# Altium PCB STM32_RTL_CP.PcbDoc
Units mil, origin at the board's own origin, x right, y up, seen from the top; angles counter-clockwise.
Board outline 3149.08 x 3872.9 mil, 2 copper layers (Top Layer, Bottom Layer); 75 components, 87 nets, 399 pads, 171 vias.
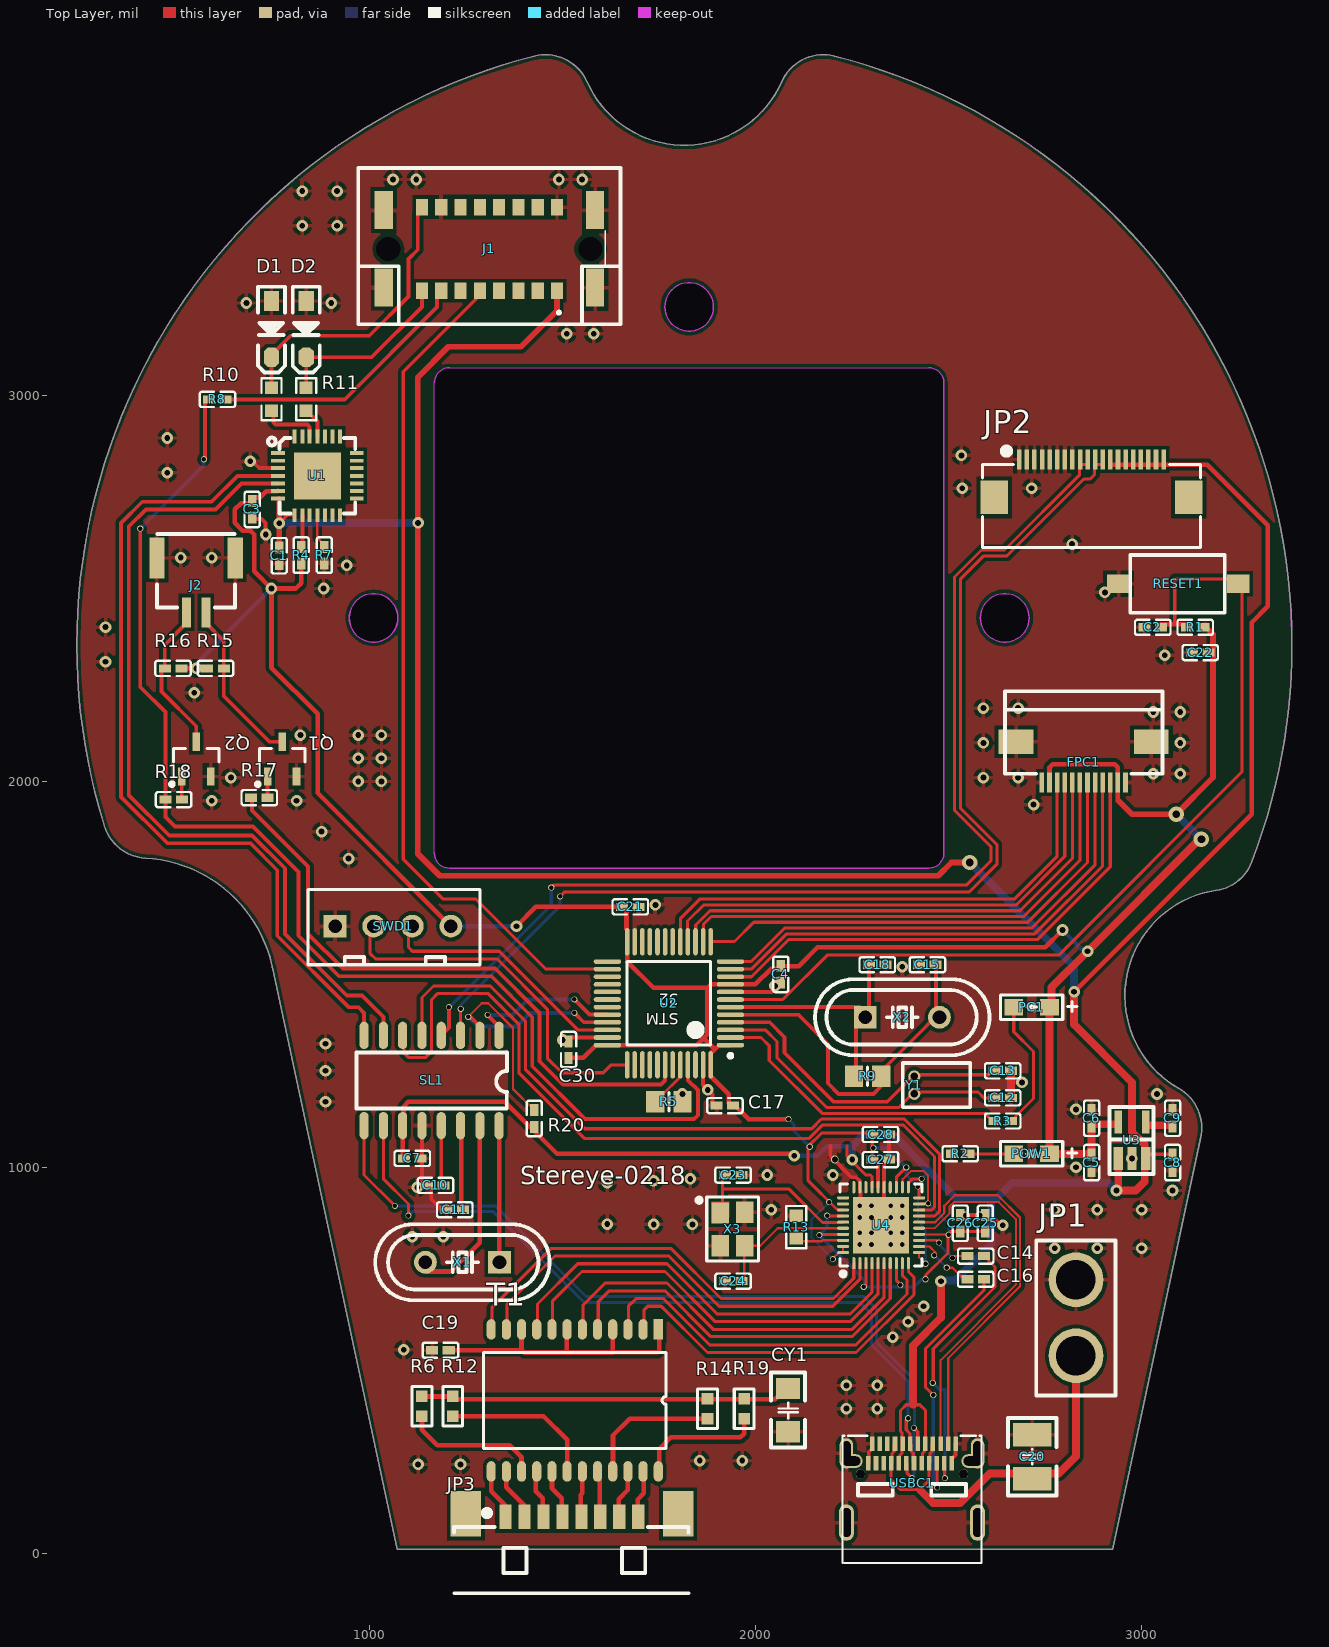
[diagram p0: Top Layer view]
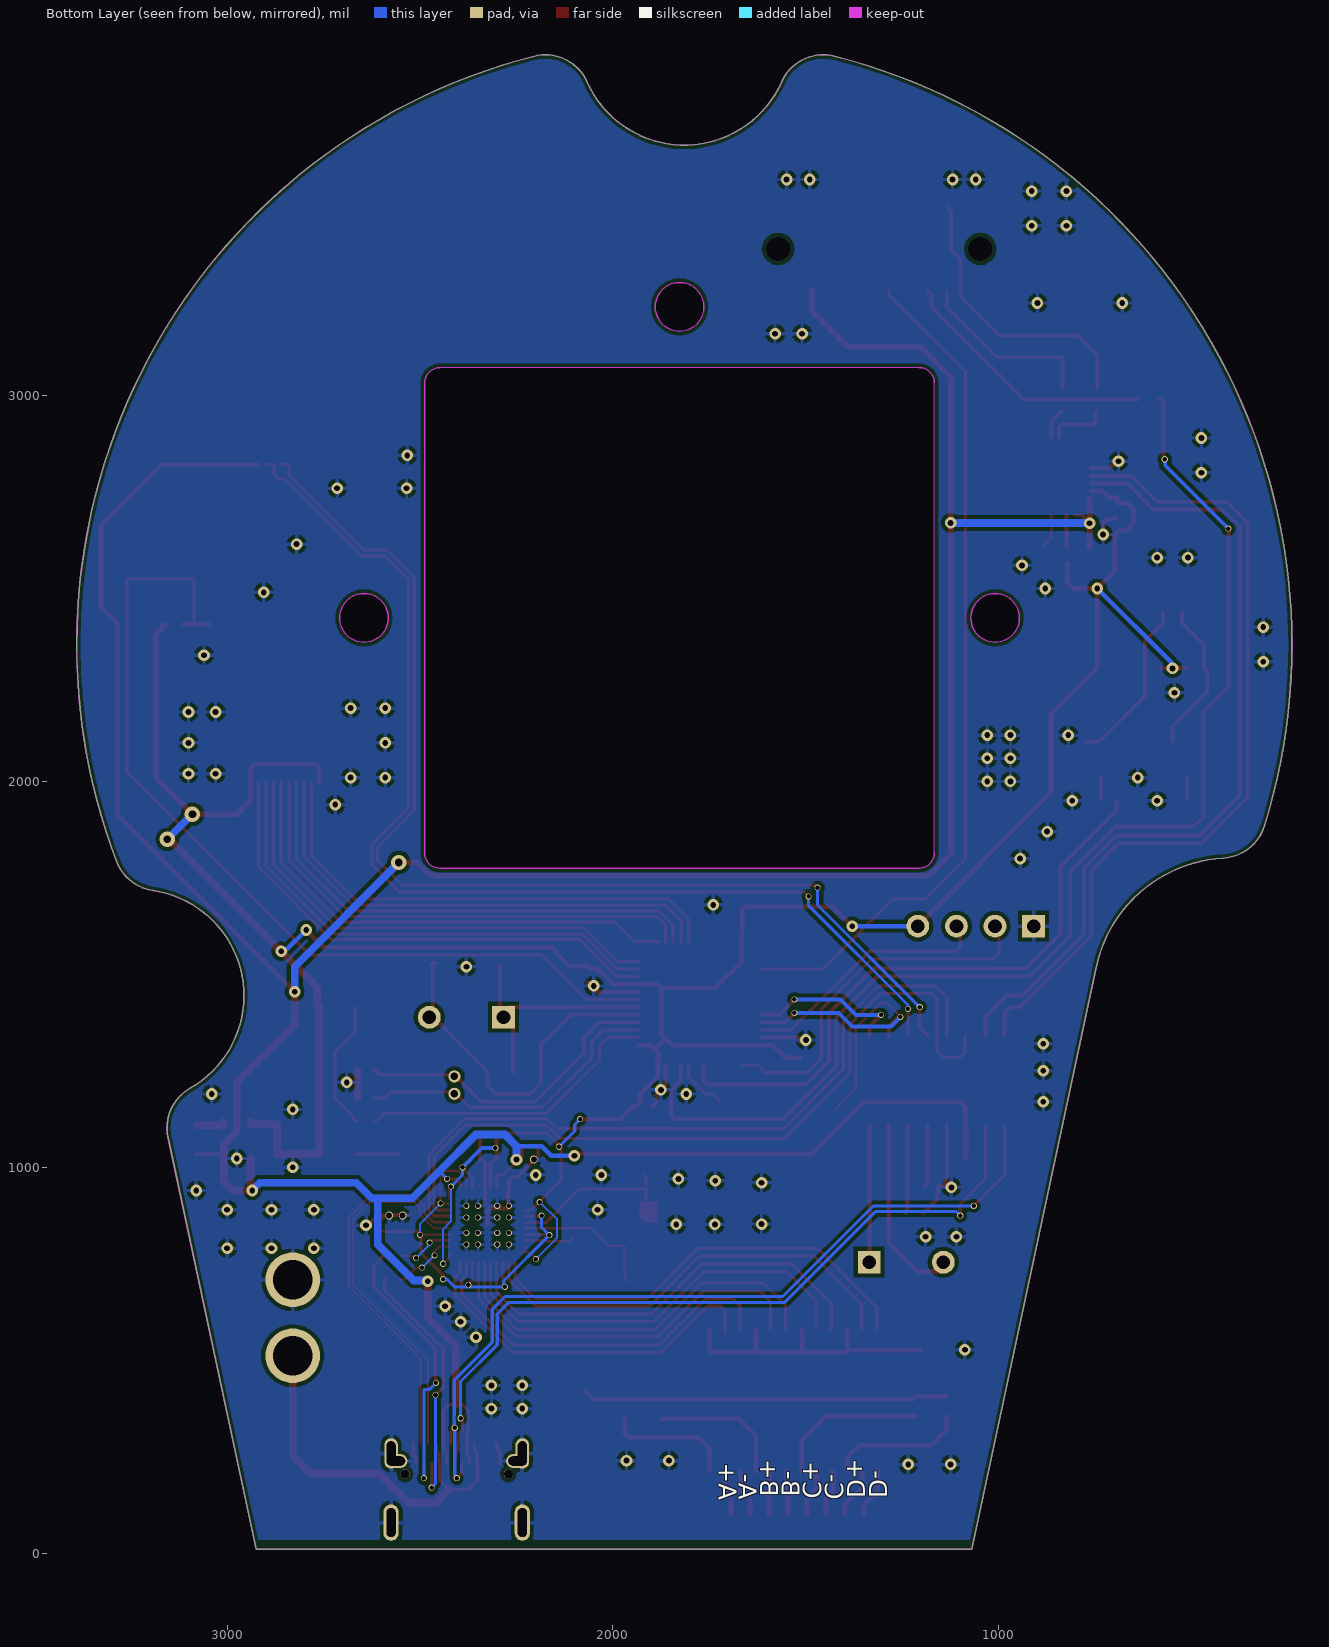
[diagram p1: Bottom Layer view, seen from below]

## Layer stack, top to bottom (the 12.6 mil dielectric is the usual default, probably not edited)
Top Solder: solder mask 0.4, Solder Resist, Dk 3.5
Top Layer: signal copper 1.4
Dielectric 1: dielectric 12.6, FR-4, Dk 4.8
Bottom Layer: signal copper 1.4
Bottom Solder: solder mask 0.4, Solder Resist, Dk 3.5

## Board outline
748.37,1514.68 ccw(c397.73,1444.47) 746.38,1523.97 ccw(c746.12,1523.91) 746.38,1523.97 ccw(c397.73,1444.47) 418.07,1801.49 cw(c424.77,1919.15) 312.29,1883.97 ccw(c312.04,1883.89) 312.29,1883.98 cw(c1815.05,2353.96) 1425.91,3879.65 cw(c1455.03,3765.46) 1425.92,3879.65 cw(c1455.03,3765.46) 1562.8,3813.15 ccw(c1815.05,3924.79) 2067.31,3813.15 cw(c2175.07,3765.46) 2204.19,3879.65 cw(c2175.07,3765.46) 2204.2,3879.65 cw(c1815.05,2353.96) 3389.59,2353.96 cw(c1815.05,2353.96) 3285.91,1792.04 ccw(c3286.15,1791.94) 3285.91,1792.03 ccw(c3286.15,1791.94) 3285.9,1792.03 ccw(c3175.82,1834.09) 3285.91,1792.03 3285.9,1792.03 cw(c3175.82,1834.09) 3192.76,1717.47 cw(c3175.82,1834.09) 3192.75,1717.47 ccw(c3232.38,1444.47) 3096.13,1204.61 cw(c3037.93,1102.14) 3155.77,1102.14 cw(c3037.93,1102.14) 3153.16,1077.48 cw(c3037.93,1102.14) 3153.16,1077.47 cw(c3153.42,1077.42) 3153.16,1077.48 3153.16,1077.47 2924.69,10.27 1070.44,10.27
cut-out: 2645.34,2360.98 cw(c2645.34,2423.98) 2582.34,2423.98 cw(c2645.34,2423.98) 2645.34,2486.97 cw(c2645.34,2423.98) 2708.33,2423.98 cw(c2645.34,2423.98)
cut-out: 1009.66,2360.98 cw(c1009.66,2423.98) 946.67,2423.98 cw(c1009.66,2423.98) 1009.66,2486.97 cw(c1009.66,2423.98) 1072.65,2423.98 cw(c1009.66,2423.98)
cut-out: 1827.5,3166.98 cw(c1827.5,3229.97) 1764.51,3229.97 cw(c1827.5,3229.97) 1827.5,3292.96 cw(c1827.5,3229.97) 1890.49,3229.97 cw(c1827.5,3229.97)
cut-out: 1206.51,1775.46 cw(c1206.51,1814.83) 1167.14,1814.83 1167.14,3033.12 cw(c1206.51,3033.12) 1206.51,3072.49 2448.49,3072.49 cw(c2448.49,3033.12) 2487.86,3033.12 2487.86,1814.83 cw(c2448.49,1814.83) 2448.49,1775.46

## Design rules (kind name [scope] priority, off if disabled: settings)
Clearance [All] p1: gap=5 ignorepadtopadclearanceinfootprint=FALSE except(10: Arc-Fill Arc-Poly Arc-Region Track-Fill Track-Poly Track-Region SMDPad-Fill SMDPad-Poly SMDPad-Region THPad-Fill THPad-Poly THPad-Region Via-Fill Via-Poly Via-Region Fill-Fill Fill-Poly Fill-Region Poly-Poly Poly-Region Region-Region)
DiffPairsRouting [All] p1: maxlimit=50 minlimit=5 mostfreqgap=5 toplayer_minwidth=5 toplayer_maxwidth=20 toplayer_prefwidth=8 bottomlayer_minwidth=5 bottomlayer_maxwidth=20 bottomlayer_prefwidth=8 maxuncoupledlength=500
PolygonConnect [All] p1: connectstyle=Relief reliefconductorwidth=10 reliefentries=4 polygonreliefangle="90 Angle" airgapwidth=10
RoutingVias [All] p1: holewidth=11.81 width=15.75 viastyle="Through Hole" minholewidth=11.81 minwidth=15.75 maxholewidth=28 maxwidth=50
SolderMaskExpansion [All] p1: expansion=4
Width All [All] p1: maxlimit=100 minlimit=5 preferedwidth=10 minimp=50.000000 maximp=50.000000 favimp=50.000000
Width VCC [InNet('5V')] p2: maxlimit=100 minlimit=5 preferedwidth=10
29 further rules are at their usual default settings.

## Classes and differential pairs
differential pair SSTX: +SSTX_P -SSTX_N
differential pair MDI3: +MDI3_P -MDI3_N
differential pair MDI2: +MDI2_P -MDI2_N
differential pair MDI1: +MDI1_P -MDI1_N
differential pair MDI0: +MDI0_P -MDI0_N
differential pair SSRX: +SSRX_P -SSRX_N
differential pair USB3-D: +USB3-D_P -USB3-D_N
differential pair D3: +D3_P -D3_N
differential pair D2: +D2_P -D2_N
differential pair D1: +D1_P -D1_N

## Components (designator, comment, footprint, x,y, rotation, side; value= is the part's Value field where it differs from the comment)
C1 "10UF" C0402_NEW 765,2585 r270 top
C2 "105" C0402_NEW 3029,2399.41 r0 top
C3 "10UF" C0402_NEW 695,2705 r90 top
C4 "104" C0402_NEW 2065,1500 r90 top
C5 "106" C0402_NEW 2870.43,1012.24 r270 top
C6 "104" C0402_NEW 2870.43,1127.24 r270 top
C7 "104" C0402_NEW 1110,1023 r180 top
C8 "105" C0402_NEW 3080.43,1012.24 r90 top
C9 "223" C0402_NEW 3080.43,1127.24 r270 top
C10 "10uF" C0402_NEW 1170,953 r0 top
C11 "10uF" C0402_NEW 1220,890.08 r0 top
C12 "22P" C0402_NEW 2640,1180 r0 top
C13 "22P" C0402_NEW 2640,1250 r0 top
C14 "0.1uF" C0402_NEW 2570,770 r0 top
C15 "22P" C0402_NEW 2445,1525 r180 top
C16 "0.1uF" C0402_NEW 2570,710 r0 top
C17 "10nf" C0402_NEW 1920,1160 r0 top
C18 "22P" C0402_NEW 2315,1525 r0 top
C19 "0.1UF" C0402_NEW 1183,526 r180 top
C20 "104" "C 1210_L" 2716.77,250 r270 top
C21 "105" C0402_NEW 1675,1675 r180 top
C22 "105" C0402_NEW 3152,2334 r0 top
C23 "30PF" C0402_NEW 1941.26,980 r0 top
C24 "30PF" C0402_NEW 1941.26,705 r0 top
C25 "10nf" C0402_NEW 2595,855 r270 top
C26 "0.1uf" C0402_NEW 2530,855 r270 top
C27 "10nf" C0402_NEW 2323.54,1020 r180 top
C28 "0.1uf" C0402_NEW 2323.54,1085 r180 top
C30 "10nf" C0402_NEW 1515,1305 r270 top
CY1 "10nF/1KV" "C 1206_L" 2084,370 r90 top
D1 "FFM107" SOD-123F 745,3172.17 r270 top
D2 "FFM107" SOD-123F 835,3172.17 r270 top
FPC1 "FPC-12P" FPC-0.5MM-12P 2850,2050 r0 top
J1 "254587" MH-16 1310,3380 r180 top
J2 "GH1.25_2P" GH1.25_2P 550,2537.99 r180 top
JP1 "HDR-1X2" XT30 2830,610 r90 top
JP2 "HDR-1X20" "FPC0.5 2H-WS-20P" 2870,2736 r0 top
JP3 "HDR-1X8" "MX 1.25-WS-8P" 1524,-16 r0 top
PC1 "LEDgreen" LED 2715,1415 r0 top
POW1 "LEDred" LED 2715,1035 r0 top
Q1 "SI2302" SOT23-3N 772.6,2057.99 r0 top
Q2 "SI2302" SOT23-3N 550,2057.99 r0 top
R1 "10K,0603" C0402_NEW 3139,2399.41 r0 top
R2 "510R,0603" C0402_NEW 2530,1035 r180 top
R3 "510R,0603" C0402_NEW 2640,1120 r180 top
R4 "5k" C0402_NEW 822,2586.54 r270 top
R5 "10K,0603" 6-0805_N 1775,1170 r0 top
R6 "1K" "R 0603_L" 1135,380.59 r270 top
R7 "5k" C0402_NEW 882,2586.54 r270 top
R8 "5k" C0402_NEW 605,2990 r180 top
R9 "1M" 6-0805_N 2290,1236.13 r0 top
R10 "68R,0603" R0603_NEW 745,2990.35 r270 top
R11 "68R,0603" R0603_NEW 835,2990.35 r270 top
R12 "1K" "R 0603_L" 1215,380.59 r270 top
R13 "2.49k" R0603_NEW 2105,845 r90 top
R14 "1K" "R 0603_L" 1875,374.41 r270 top
R15 "510R,0603" C0402_NEW 600,2292.99 r180 top
R16 "510R,0603" C0402_NEW 490,2292.99 r0 top
R17 "68R,0603" C0402_NEW 713.54,1957.99 r180 top
R18 "68R,0603" C0402_NEW 491.46,1952.99 r180 top
R19 "1K" "R 0603_L" 1970,374.41 r270 top
R20 "5k" C0402_NEW 1426,1126.54 r90 top
RESET1 "SW-PB" Key 2940.46,2512.05 r180 top
SL1 "SL2.1A" SOP-16_L10.0-W3.9-P1.27-LS6.0-BL 1160,1225 r180 top
SWD1 "SWD" HDR1X4H 910,1625 r0 top
T1 "SG24002g" SG24002 1747.48,580 r270 top
U1 "CP2102" CP2102-28G 864,2792 r0 top
U2 "STM32F103C8T6" STM32-48P 1775,1425 r180 top
U3 "RT9193-33GB" SOT-23-5 2975,1070 r0 top
U4 "RTL8153B-VB-CG" QFN-40_L5.0-W5.0-P0.40-BL-EP3.7 2325,850 r0 top
USBC1 "TypeC SMD" USB-C-SMD_MC-312D-C 2405,139.69 r0 top
X1 "12MHz" XTAL 1240,754.01 r180 top
X2 "8MHz" XTAL 2380,1388.94 r0 top
X3 "25MHz" OSC-SMD_4P-L3.2-W2.5-BL 1940,840 r90 top
Y1 "32.768K" XLAT-32 2410.98,1235.5 r270 top

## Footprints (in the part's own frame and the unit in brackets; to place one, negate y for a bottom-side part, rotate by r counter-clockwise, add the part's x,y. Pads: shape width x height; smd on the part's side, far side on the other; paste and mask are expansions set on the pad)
6-0805_N [mm] "Chip Resistor, Body 2.0x1.2mm, IPC Medium Density"
  rect 1.2x1.4 smd: 1(-0.9,0) 2(0.9,0)
  silkscreen extent 0,-0.6 0,0.6, body extent -1.07,-0.7 1.07,0.7, height 0.7
C0402_NEW [mm]
  rect 0.79x0.54 smd: 1(-0.545,0) 2(0.545,0)
  silkscreen extent -1.17,-0.5 1.17,0.5
"C 1206_L" [mil] "无极性贴片电容"
  rect 55x62 smd: 1(-55.12,0) 2(57.09,0)
  silkscreen extent -96,-44 98,44, body extent -63,-32 63,32, height 48
"C 1210_L" [mil] "无极性贴片电容                                淘宝ID:黄晶宝石"
  rect 60x100 smd: 1(-57.09,0) 2(57.09,0)
  silkscreen extent -100,-63 100,63, body extent -63,-51 63,51, height 60
CP2102-28G [mil]
  rect 35.4x10 smd: 1(-102,59) 2(-102,39) 3(-102,20) 4(-102,0) 5(-102,-20) 6(-102,-39) 7(-102,-59) 15(102,-59) 16(102,-39) 17(102,-20) 18(102,0) 19(102,20) 20(102,39) 21(102,59)
  rect 10x35.4 smd: 8(-59,-102) 9(-39,-102) 10(-20,-102) 11(0,-102) 12(20,-102) 13(39,-102) 14(59,-102) 22(59,102) 23(39,102) 24(20,102) 25(0,102) 26(-20,102) 27(-39,102) 28(-59,102)
  rect 122x122 smd: 29(0,0)
  silkscreen extent -128,-98 98,99
"FPC0.5 2H-WS-20P" [mm] "长：14.2mm，宽：5.2mm，高：2mm  淘宝ID:黄晶宝石   店铺网址:https://shop463601444.taobao.com"
  rect 1.8x2.2 smd: 0(-6.4,0) 0(6.4,0)
  rect 0.3x1.3 smd: 1(-4.75,2.497) 2(-4.25,2.497) 3(-3.75,2.497) 4(-3.25,2.497) 5(-2.75,2.497) 6(-2.25,2.497) 7(-1.75,2.497) 8(-1.25,2.497) 9(-0.75,2.497) 10(-0.25,2.497) 11(0.25,2.497) 12(0.75,2.497) 13(1.25,2.497) 14(1.75,2.497) 15(2.25,2.497) 16(2.75,2.497) 17(3.25,2.497) 18(3.75,2.497) 19(4.25,2.497) 20(4.75,2.497)
  silkscreen extent -7.18,-3.3 7.18,3.23, body extent -7.1,-3.15 7.1,2.85, height 2
FPC-0.5MM-12P [mm]
  rect 0.3x1.3 smd: 1(-2.751,-1.341) 2(-2.252,-1.341) 3(-1.751,-1.341) 4(-1.251,-1.341) 5(-0.751,-1.341) 6(-0.25,-1.341) 7(0.25,-1.341) 8(0.749,-1.341) 9(1.248,-1.341) 10(1.749,-1.341) 11(2.249,-1.341) 12(2.75,-1.341)
  rect 2.286x1.6 smd: 13(4.45,1.34) 14(-4.45,1.34)
  silkscreen extent -5.18,-0.76 5.18,4.67
GH1.25_2P [mm]
  rect 0.6x2 smd: 1(-0.635,2.54) 2(0.635,2.54)
  rect 1x2.7 smd: 3(2.585,-1.041) 4(-2.565,-1.041)
  silkscreen extent -2.55,-2.62 2.57,2.21
HDR1X4H [mm] "Connector; Header; 4 Position; Right Angle"
  rect 1.5x1.5 hole 0.9: 1(0,0)
  round 1.5 hole 0.9: 2(2.54,0) 3(5.08,0) 4(7.62,0)
  silkscreen extent -1.78,-2.54 9.52,2.41
Key [mil]
  rect 59.06x47.24 smd: 1(0,0) 2(-310,0)
  silkscreen extent -275,-75 -30,75
LED [mil]
  rect 49x43 smd: 1(46.26,0) 2(-46.26,0)
  silkscreen extent -81,-31 118,31
MH-16 [mm]
  rect 0.8x1.1 smd: A1(4.445,-2.75) A2(3.175,-2.75) A3(1.905,-2.75) A4(0.635,-2.75) A5(-0.635,-2.75) A6(-1.905,-2.75) A7(-3.175,-2.75) A8(-4.445,-2.75) B1(4.445,2.75) B2(3.175,2.75) B3(1.905,2.75) B4(0.635,2.75) B5(-0.635,2.75) B6(-1.905,2.75) B7(-3.175,2.75) B8(-4.445,2.75)
  round 0.8 hole 1.6 unplated: MH1(-6.655,0) MH2(6.655,0)
  rect 1.2x2.5 smd: MP1(-6.955,2.55) MP2(-6.955,-2.55) MP3(6.955,2.55) MP4(6.955,-2.55)
  silkscreen extent -8.64,-5.33 8.64,4.95, body extent -7.62,-3.5 7.62,3.5, height 6.7
"MX 1.25-WS-8P" [mm] "长：15.15mm，宽：4.2mm，高：3.4mm"
  rect 2x3 smd: 0(-7,3) 0(7,3)
  rect 0.8x1.6 smd: 1(-4.389,2.811) 2(-3.139,2.811) 3(-1.889,2.811) 4(-0.639,2.811) 5(0.611,2.811) 6(1.861,2.811) 7(3.111,2.811) 8(4.361,2.811)
  silkscreen extent -7.77,-2.23 7.67,3.25, body extent -7.57,-2.1 7.57,3.09, height 3.4
OSC-SMD_4P-L3.2-W2.5-BL [mm]
  rect 1.4x1.15 smd: 1(1.059,0.8) 2(-1.1,0.8) 3(-1.1,-0.8) 4(1.1,-0.8)
  Top Layer region: 1.8,0.225 0.762,0.225 0.4,0.604 0.4,1.375 1.8,1.375
  silkscreen extent -2.1,-1.7 2.1,2.35
QFN-40_L5.0-W5.0-P0.40-BL-EP3.7 [mm]
  oval 0.2x0.8 smd: 1(-1.8,-2.499) 2(-1.4,-2.499) 3(-1,-2.499) 4(-0.6,-2.499) 5(-0.2,-2.499) 6(0.2,-2.499) 7(0.6,-2.499) 8(1,-2.499) 9(1.4,-2.499) 10(1.8,-2.499) 21(1.8,2.499) 22(1.4,2.499) 23(1,2.499) 24(0.6,2.499) 25(0.2,2.499) 26(-0.2,2.499) 27(-0.6,2.499) 28(-1,2.499) 29(-1.4,2.499) 30(-1.8,2.499)
  oval 0.8x0.2 smd: 11(2.499,-1.8) 12(2.499,-1.4) 13(2.499,-1) 14(2.499,-0.6) 15(2.499,-0.2) 16(2.499,0.2) 17(2.499,0.6) 18(2.499,1) 19(2.499,1.4) 20(2.499,1.8) 31(-2.499,1.8) 32(-2.499,1.4) 33(-2.499,1) 34(-2.499,0.6) 35(-2.499,0.2) 36(-2.499,-0.2) 37(-2.499,-0.6) 38(-2.499,-1) 39(-2.499,-1.4) 40(-2.499,-1.8)
  rect 3.7x3.7 smd: 41(0,0)
  silkscreen extent -2.7,-3.35 2.7,2.7
R0603_NEW [mil]
  rect 31.75x34.02 smd: 1(-29.65,0) 2(29.66,0)
  silkscreen extent -55,-26 55,26
"R 0603_L" [mil] "1/10W贴片电阻                 淘宝ID:黄晶宝石"
  rect 30x30 smd: 1(-25.59,0) 2(25.59,0)
  silkscreen extent -51,-26 51,26, body extent -31,-16 32,16, height 16
SG24002 [mm]
  rect 1.35x0.6 smd: 1(0,0)
  oval 1.35x0.6 smd: 2(0,-1) 3(0,-2) 4(0,-3) 5(0,-4) 6(0,-5) 7(0,-6) 8(0,-7) 9(0,-8) 10(0,-9) 11(0,-10) 12(0,-11) 13(9.35,-11) 14(9.35,-10) 15(9.35,-9) 16(9.35,-8) 17(9.35,-7) 18(9.35,-6) 19(9.35,-5) 20(9.35,-4) 21(9.35,-3) 22(9.35,-2) 23(9.35,-1) 24(9.35,0)
  silkscreen extent 1.51,-11.5 7.84,0.5
SOD-123F [mm] "2.7x1.6X1.1mm（长宽高，不包括引脚）"
  rect 1.3x1 smd: 1(-1.85,0)
  oct 1.3x1 smd: 2(1.85,0)
  silkscreen extent -2.79,-0.89 2.84,0.89, body extent -1.9,-0.8 1.9,0.8, height 1.15
SOP-16_L10.0-W3.9-P1.27-LS6.0-BL [mm]
  oval 0.6x1.8 smd: 1(-4.445,-2.972) 2(-3.175,-2.972) 3(-1.905,-2.972) 4(-0.635,-2.972) 5(0.635,-2.972) 6(1.905,-2.972) 7(3.175,-2.972) 8(4.445,-2.972) 9(4.445,2.972) 10(3.175,2.972) 11(1.905,2.972) 12(0.635,2.972) 13(-0.635,2.972) 14(-1.905,2.972) 15(-3.175,2.972) 16(-4.445,2.972)
  silkscreen extent -4.95,-1.85 4.95,1.85
SOT23-3N [mm] "3x1.3x1mm(长宽高)    封装库来自淘宝卖家 ID：黄晶宝石"
  rect 0.5x1.2 smd: 1(-0.95,-1.143) 2(0.95,-1.143) 3(0,1.143)
  silkscreen extent -1.72,-1.78 1.5,0.7, body extent -1.5,-1.2 1.5,1.2, height 1.05
SOT-23-5 [mm]
  rect 0.6x1.5 smd: 1(-0.9,-1.2) 2(0,-1.2)
  rect 0.63x1.5 smd: 3(0.9,-1.2)
  rect 0.5x1.5 smd: 4(0.9,1.2) 5(-0.9,1.2)
  silkscreen extent -1.47,-2.21 1.43,2.18
STM32-48P [mm]
  oval 1.8x0.3 smd: 1(-4.05,2.75) 2(-4.05,2.25) 3(-4.05,1.75) 4(-4.05,1.25) 5(-4.05,0.75) 6(-4.05,0.25) 7(-4.05,-0.25) 8(-4.05,-0.75) 9(-4.05,-1.25) 10(-4.05,-1.75) 11(-4.05,-2.25) 12(-4.05,-2.75) 25(4.05,-2.75) 26(4.05,-2.25) 27(4.05,-1.75) 28(4.05,-1.25) 29(4.05,-0.75) 30(4.05,-0.25) 31(4.05,0.25) 32(4.05,0.75) 33(4.05,1.25) 34(4.05,1.75) 35(4.05,2.25) 36(4.05,2.75)
  oval 0.3x1.8 smd: 13(-2.75,-4.05) 14(-2.25,-4.05) 15(-1.75,-4.05) 16(-1.25,-4.05) 17(-0.75,-4.05) 18(-0.25,-4.05) 19(0.25,-4.05) 20(0.75,-4.05) 21(1.25,-4.05) 22(1.75,-4.05) 23(2.25,-4.05) 24(2.75,-4.05) 37(2.75,4.05) 38(2.25,4.05) 39(1.75,4.05) 40(1.25,4.05) 41(0.75,4.05) 42(0.25,4.05) 43(-0.25,4.05) 44(-0.75,4.05) 45(-1.25,4.05) 46(-1.75,4.05) 47(-2.25,4.05) 48(-2.75,4.05)
  silkscreen extent -4.18,-2.75 2.75,3.57, body extent -3.5,-3.5 3.5,3.5, height 1.6
USB-C-SMD_MC-312D-C [mm]
  oval 0.9x2 hole 0.6 slot 1.6 at 90 deg: 1(-4.32,3.018) 2(4.32,3.018)
  oval 1.5x0.9 hole 0.6 slot 1.2 at 0 deg: 1(-4,2.518) 2(4,2.518)
  oval 1x2.4 hole 0.6 slot 1.9 at 90 deg: 3(4.32,-1.532) 4(-4.32,-1.532)
  rect 0.3x0.95 smd: A1(-2.62,3.668) A2(-2.12,3.668) A3(-1.62,3.668) A4(-1.12,3.668) A5(-0.62,3.668) A6(-0.12,3.668) A7(0.38,3.668) A8(0.88,3.668) A9(1.38,3.668) A10(1.88,3.668) A11(2.38,3.668) A12(2.88,3.668) B1(2.63,2.368) B2(2.13,2.368) B3(1.63,2.368) B4(1.13,2.368) B5(0.63,2.368) B6(0.13,2.368) B7(-0.37,2.368) B8(-0.87,2.368) B9(-1.37,2.368) B10(-1.87,2.368) B11(-2.37,2.368) B12(-2.87,2.368)
  round 0.6 hole 0.6 unplated: ""(-3.4,1.668) ""(3.4,1.668)
  silkscreen extent -4.57,-4.2 4.57,4.18
XLAT-32 [mm]
  round 0.8 hole 0.5: 0(0,0) 1(1.143,0)
  silkscreen extent -0.89,-0.76 2.03,3.68
XT30 [mm]
  round 3.6 hole 2.6: 1(-2.5,0) 2(2.5,0)
  silkscreen extent -5.12,-2.59 5.09,2.62
XTAL [mm]
  rect 1.5x1.5 hole 0.9: 1(-2.44,0)
  round 1.5 hole 0.9: 2(2.44,0)
  silkscreen extent -5.74,-2.5 5.74,2.5

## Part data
C1 C3: library part 47uf, BOM_Manufacturer Part=?
C2 C4 C5 C6 C7 C8 C9 C12 C13 C15 C18 C20 C21 C22: BOM_Manufacturer=YAGEO, BOM_Manufacturer Part=CC0603KRX7R9BB104
C10 C11: BOM_JLCPCB Part Class="Extended Part", BOM_Manufacturer=SAMSUNG, BOM_Manufacturer Part=CL10A106MP8NNNC
CY1: library part CY, "安规Y电容"
D1 D2: "快恢复整流二极管"
FPC1: BOM_Manufacturer=JUSHUO, BOM_Manufacturer Part=AFC01-S12FCA-00
J1: "Connector", Manufacturer_Name=ERNI, Mouser Part Number=305-254587
JP1: library part "Header 2", "2P接插件"
JP2: library part "Header 20", "20P接插件"
JP3: library part "Header 8", "8P接插件"
PC1 POW1: library part LED
Q1 Q2: "N沟道场效应管"
R1 R5: BOM_Manufacturer=UniOhm, BOM_Manufacturer Part=060300J0103T5E
R2 R3 R15 R16: BOM_Manufacturer=UniOhm, BOM_Manufacturer Part=0603WAJ0511T5E
R4 R7 R8 U1: BOM_Manufacturer Part=?
R6 R12 R14 R19: library part R, "贴片电阻"
R9: library part 1M0603, BOM_Manufacturer="Uniroyal Elec", BOM_Manufacturer Part=0603WAF1054T5E
R10 R11 R17 R18 R20: library part 510R,0603, BOM_Manufacturer=UniOhm, BOM_Manufacturer Part=0603WAJ0511T5E
SL1: BOM_LCSC Assembly=Yes, BOM_Manufacturer=CoreChips
SWD1: BOM_Manufacturer=Ckmtw, BOM_Manufacturer Part="210S-1*4P L{}11.6MMGold-plated black"
U3: BOM_Manufacturer=RICHTEK, ICA_PARTNUM=$$2191094$$RT9193-15CU5, Part Number=TMP-13
U4: BOM_JLCPCB Part Class="Extended Part", BOM_Manufacturer=REALTEK(瑞昱)
X1: BOM_JLCPCB Part Class="Extended Part", BOM_Manufacturer=YXC, BOM_Manufacturer Part=X49SD12MSD2SC
X2: BOM_Manufacturer="ZheJiang East Crystal Elec", BOM_Manufacturer Part=B08000J065
X3: BOM_LCSC Assembly=Yes, BOM_Manufacturer="Zhejiang Abel Elec", BOM_Manufacturer Part=SMD-3225_4P25MHZ12PF10PPM-40~+85℃
Y1: library part XLAT-32, BOM_Manufacturer=KDS, BOM_Manufacturer Part="DST310S 32.768KHz"

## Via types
v1: diameter 30, hole 15, Top Layer to Bottom Layer, 110 vias
v2: diameter 15.75, hole 11.81, Top Layer to Bottom Layer, 55 vias
v3: diameter 20, hole 15.75, Top Layer to Bottom Layer, 3 vias
v4: diameter 40, hole 20, Top Layer to Bottom Layer, 3 vias

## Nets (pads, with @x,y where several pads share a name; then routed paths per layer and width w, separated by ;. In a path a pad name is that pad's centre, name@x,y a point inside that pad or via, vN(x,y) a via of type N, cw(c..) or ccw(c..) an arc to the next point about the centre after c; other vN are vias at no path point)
1V0: C25.2 C26.2 U4.3 U4.8 U4.14 U4.19 U4.22 U4.34 U4.37 | length 1256.4
  Top Layer w5: U4.22 2380.67,948.95 2380.67,969.27 2396.03,984.63 2396.37,984.63 2401.74,990 2435,990 2446.65,978.35 v2(2446.65,906.65) 2424.93,906.65 U4.19 ; U4.14 v2@2500,826.38
  Top Layer w8: v2(2165,824.25) 2167.1,824.25 2169.22,826.38 U4.37 ; v2(2185,875) 2186.32,873.69 2226.54,873.69 U4.34 ; v2(2280,690) 2280.94,690 2285.63,694.69 U4.3 ; U4.8 2364.43,751.54 2364.43,707.66 2375,697.1 v2(2375,695) ; v2(2440,710) 2440,720 2498.13,778.13 v2@2498.13,823.13 ; v2(2500,825) 2500,826.38 2500,830 2503.54,833.54 C26.2 C25.2
  Bottom Layer w5: v2(2446.65,906.65) 2500,853.3 v2(2500,825)
  Bottom Layer w8: v2(2185,875) 2185,844.25 v2(2165,824.25) 2282.4,706.86 2282.4,692.4 v2(2280,690) 2410,690 2430,710 v2(2440,710)
3V3: C3.2 C4.2 C5.1 C6.2 C17.2 C21.2 C22.2 C27.2 C28.2 C30.2 FPC1.2 FPC1.11 PC1.1 POW1.1 R1.2 R4.2 R15.2 R16.2 SWD1.4 U1.6 U2.1 U2.9 U2.24 U2.36 U2.48 U3.5 U4.11 U4.20 U4.23 U4.26 U4.33 U4.39 U4.40 | length 8533.9
  Top Layer w5: v2@2200,760 v2(2200,762.17) 2200,764.35 2214.79,779.13 U4.40 U4.39 ; U4.11 2423.4,766.6 v2(2440,750)
  Top Layer w8: U4.33 2214.91,889.37 2212.1,892.18 2209.43,892.18 2135,966.61 2135,1053.23 2170.88,1089.12 2297.97,1089.12 C28.2 ; U4.23 2364.43,948.46 2364.43,974.43 v2(2390,1000) ; v2(2420,950) 2423.4,946.6 U4.20
  Top Layer w10: C28.2 C27.2 2307.01,1020 2317.13,1009.88 U4.26
  Top Layer w12: R16.2 v1(550,2292.99) R15.2 ; 649.97,2695.03 649.97,2704.97 666.37,2721.37 690.37,2721.37 695,2726 C3.2 ; 650,2695 650,2670 670,2650 690,2650 700,2640 700,2545 v1(745,2500) ; C3.2@690,2726.46 690,2731.38 694.63,2736.01 716.01,2736.01 732,2752 761,2752 U1.6 ; R4.2 822,2514.03 807.97,2500 v1(745,2500) ; SWD1.4 865,1970 865,2175 745,2295 v1(745,2500) ; v1(1380,1625) 1430,1675 C21.2 1658.47,1675 1665.09,1668.37 1665.09,1616.64 1666.73,1615.01 U2.24 1666.73,1533.27 1735,1465 1875,1465 ; C30.2 1552.83,1283.54 1586.02,1316.73 U2.36 1846.47,1316.73 1860.74,1331 ; U2.1@1903.89,1316.73 U2.1@1904.92,1316.73 ; U2.1 U2.1@1904.92,1316.73 ; v2@2080,1125 1981.38,1125 1946.38,1160 C17.2 1936.54,1160 1929.91,1166.63 1929.91,1189.39 1883.27,1236.02 U2.48 1883.27,1295.08 1894.09,1305.91 ; FPC1.2 2761.45,1997.32 2761.45,2036.44 2770,2045 2930,2045 2938.45,2036.55 2938.45,1997.32 FPC1.11 2938.55,1951.45 2940,1950 ; v1(2795,1615) 2750,1570 2160,1570 2111.46,1521.46 C4.2 2058.54,1515 2040,1515 1999.21,1474.21 U2.9 1884.21,1474.21 1875,1465 ; 1860.74,1331 1875,1345.26 1875,1465 ; 1860.74,1331 1869,1331 1894.09,1305.91 ; 1894.09,1305.91 U2.1@1904.92,1316.73
  Top Layer w15: 2940,1950 2975,1915 v4(3090,1915) 3185,2010 3185,2381.46 3161.46,2405 R1.2@3166.38,2405
  Top Layer w20: U3.5 2939.57,1111.5 2939.41,1111.34 2871.06,1111.34 2870.43,1110.71 C6.2 C5.1 2869.8,1034.35 2761.91,1034.35 POW1.1 PC1.1 2766.5,1420.24 2766.5,1466.5 v1(2860,1560) v4@3150,1850
  Bottom Layer w5: v2(2190,910) 2145,865 2145,817.17 v2(2200,762.17) ; v2(2420,950) 2420,860 2440,840 v2(2440,750)
  Bottom Layer w8: v2(2085,1125) 2099.05,1110.95 2099.05,1094.18 v2(2140,1053.23) ; v2(2390,1000) 2390,980 v2(2420,950)
  Bottom Layer w10: v2(2305,1050) 2340,1050 v2(2390,1000)
  Bottom Layer w12: v1(550,2292.99) 553.44,2296.43 553.44,2308.44 v1(745,2500) ; SWD1.4 v1(1380,1625) ; v1(2795,1615) 2846.56,1563.44 2856.56,1563.44 v1(2860,1560)
  Bottom Layer w20: v4@3085,1915 v4(3090,1915) v4(3155,1850)
5V: C1.1 C7.2 C8.2 J1.B8 JP2.13 JP2.14 JP2.15 JP2.16 JP2.17 JP2.18 JP2.19 JP2.20 R20.1 SL1.11 U1.7 U1.8 U3.1 U3.3 U4.21 U4.27 USBC1.A5 USBC1.A8 USBC1.B5 USBC1.B8 | length 10295.9
  Top Layer w8: U1.7 764,2733 U1.7@765,2732 ; v1(765,2669.23) 785.77,2690 U1.8 ; C7.2@1085,1026.54 C7.2 ; 2236.46,1055 2236.46,1028.54 2285,980 2297.53,980 2301.38,976.15 U4.27 ; USBC1.B8 2372.66,234.82 2372.66,252.47 2378.68,258.5 USBC1.A5@2378.68,286 ; USBC1.A5 USBC1.A5@2378.68,286 ; U4.21 2395.87,960.09 2405.78,970 v2(2430,970) ; USBC1.B5 2431.71,234.82 2431.71,258.51 2437.74,264.54 2437.74,282.19 USBC1.A8 2440,284.44 2440,370 2425.31,384.69 2407.66,384.69 2390,384.69 2375,369.69 2375,316.3 2378.68,312.62 USBC1.A5@2378.68,286
  Top Layer w10: U3.3 3021.38,1033.7 C8.2
  Top Layer w12: C7.2@1085,1026.54 SL1.11 1087.22,1110.22 1087.22,1157.22 1100,1170 1350,1170 1485,1035 v1@2100,1035 ; v1(2825,1455) 3285,1915 3285,2412 3326.99,2453.99 3326.99,2664.01 3170,2821 JP2.13@2919.21,2821
  Top Layer w15: C1.1 v1(765,2669.23) U1.7@765,2732 ; J1.B8 1485,3220 1391.57,3126.56 1203.43,3126.56 1124,3047.13 1124,2670 1124,1812.72 1181.25,1755.46 2473.08,1755.46 2507.62,1790 v4(2555,1790)
  Top Layer w20: 2407.66,384.69 2407.66,537.66 2480,610 v1(2480,705) ; v1(2825,1455) 2825,1370 2975,1220 2975,1092.09 3008.03,1059.06 3008.03,1025.16 U3.3 3008.23,1020.55 3008.23,963.23 2985,940 2937.71,940 v1@2935,942.71 ; v1(2935,940) v1@2935,942.71 ; U3.1 2939.57,947.27 v1@2935,942.71
  Bottom Layer w8: v2(2430,970) 2445,985 2445,995
  Bottom Layer w12: v1(2100,1030) 2160,1030 2185,1055 2250,1055
  Bottom Layer w20: v1(765,2669.23) 765.38,2669.61 1124.62,2669.61 v1(1125,2670) ; v1(2250,1020) 2250,1055 2280,1085 2355,1085 2445,995 2520,920 2610,920 ; v1(2480,705) 2481.91,706.91 2516.91,706.91 2610,800 2610,920 ; v4(2555,1790) 2825,1520 v1(2825,1455) ; v1(2935,940) 2915,960 2665,960 2625,920 2610,920
BOOT0: R5.1 U2.44 | length 140
  Top Layer w8: R5.1@1724.57,1170 1724.57,1173.94 1740.63,1190 1759.9,1190 1799.75,1229.85 1799.75,1230.21 1804.53,1234.99 U2.44
BOOT1: U2.20
D1_N: SL1.7 U1.5 | length 2174.2
  Top Layer w10: U1.5 667,2772 600,2705 420,2705 375,2660 375,1965 480,1860 695,1860 780,1775 780,1605 940,1445 980,1445 1035,1390 SL1.7
D1_P: SL1.8 U1.4 | length 2187.1
  Top Layer w10: U1.4 657,2792 590,2725 410,2725 355,2670 355,1960 475,1840 690,1840 760,1770 760,1600 945,1415 970,1415 985,1400 SL1.8
D2_N: SL1.1 U2.32 | length 408.9
  Top Layer w10: v2(1305,1395) 1335,1365 SL1.1 ; v2(1530,1435) 1569.18,1395.82 1615.21,1395.82 U2.32
  Bottom Layer w10: v2(1305,1395) 1370,1395 1410,1435 v2(1530,1435)
D2_P: R20.2 SL1.2 U2.33 | length 851.9
  Top Layer w6: v2(1255,1390) 1290,1425 1307,1425 1371,1361 1371,1203 R20.2
  Top Layer w10: v2(1255,1390) 1260.62,1390 1285,1365.62 SL1.2 ; v2(1530,1400) 1554.21,1375.79 U2.33
  Bottom Layer w10: v2(1255,1390) 1280,1365 1380,1365 1415,1400 v2(1530,1400)
D3_N: JP2.11 JP2.12 SL1.3 | length 2918.2
  Top Layer w8: SL1.3 1235,1410 v2(1235.62,1410.62) ; v2(1493,1702) 1505,1714 2554,1714 2625,1785 2625,1836.63 2530.29,1931.33 2530.29,2523.66 2591.34,2584.71 2651.07,2584.71 2850.38,2784.02 2866.71,2784.02 2877.94,2795.25 2877.94,2819.79 2879.84,2821.69 JP2.12@2899.53,2821.69
  Bottom Layer w8: v2(1235.62,1410.62) 1235.62,1420.62 1493,1678 v2(1493,1702)
D3_P: JP2.9 JP2.10 SL1.4 | length 2925.8
  Top Layer w8: v2(1470,1725) 1477,1732 2547,1732 2610,1795 2610,1830 2515,1925 2515,2530 2585,2600 2644.73,2600 2839.57,2794.83 2839.57,2820.79 2840.47,2821.69 JP2.10@2860.16,2821.69
  Top Layer w10: SL1.4 1205,1362 v2(1205,1415)
  Bottom Layer w8: v2(1205,1415) 1205.36,1415 1470,1679.64 v2(1470,1725)
GND: C1.2 C2.1 C3.1 C4.1 C5.2 C6.1 C7.1 C8.1 C9.1 C10.1 C11.1 C12.2 C13.2 C15.2 C17.1 C18.2 C19.2 C20.1 C21.1 C22.1 C23.2 C24.1 C25.1 C26.1 C27.1 C28.1 C30.1 CY1.1 D1.1 D2.1 FPC1.1 FPC1.12 FPC1.13 FPC1.14 J1.A2 J1.A8 J1.MP1 J1.MP2 J1.MP3 J1.MP4 J2.3 J2.4 JP1.2 JP2.1 JP2.2 JP2.3 JP2.4 JP2.5 JP2.6 JP2.7 JP2.8 Q1.2 Q2.2 R2.2 R5.2 R7.2 R13.2 RESET1.1 SL1.12 SWD1.1 U1.3 U2.8 U2.23 U2.35 U2.47 U3.2 U4.25 U4.29 U4.41 USBC1.1 USBC1.2 USBC1.3 USBC1.4 USBC1.A1 USBC1.A12 USBC1.B1 USBC1.B12 X3.2 X3.4 | length 1580.6
  Top Layer w10: v1(690,2830) 695.41,2830 713.41,2812 U1.3 ; C3.1 698.54,2680 720,2680 730,2670 v1(730,2640) ; C7.1 C7.1@1135,1026.54 ; SL1.12 C7.1@1135,1026.54 ; C11.1@1198.54,883 1193.62,883 1159.09,917.52 1159.09,947.37 1153.46,953 C10.1 1143.62,953 1137.99,958.63 1137.99,963.55 1135,966.54 C7.1@1135,1026.54 ; C30.1 1515,1330.79 1520.63,1336.42 U2.35 ; U2.47 1863.58,1212.79 v1(1875.79,1200.58) 1887.99,1188.38 1887.99,1165.63 1893.62,1160 C17.1 ; U2.8 2040.99,1454.53 2054.45,1467.99 2059.37,1467.99 2065,1473.62 C4.1 ; 2193.54,1055 2193.54,1028.97 2248.36,974.15 2259.91,974.15 2269.88,964.17 U4.29 2269.88,939.65 2271.69,937.83 2271.69,893.28 2325,893.28 U4.41 ; USBC1.B12 2292.92,233.82 2292.92,262.36 2301.85,271.3 USBC1.A1 ; U4.41@2332.13,905 2332.13,1012.05 2340.08,1020 C27.1 C28.1 ; USBC1.B1 2508.54,245.71 2517.48,254.65 2517.48,283.19 USBC1.A12 ; C26.1 2580,876.46 2590.08,876.46 C25.1@2595,871.53 ; C25.1 C25.1@2595,871.53 ; v1(2640,850) 2634.59,850 2618.68,865.9 2600.63,865.9 C25.1@2595,871.53
  Top Layer w20: C12.2 C13.2
  other v1: 1125,230 1235,230 1855,240 1965,240 2235,374.69 2315,374.69 2235,434.69 2315,434.69 1088,527 2355,560 2395,600 2435,640 2775,790 2885,790 3000,790 1110,820 1190,820 1736,852 1836,852 1615,853 2040,890 2775,890 2885,890 3000,890 3080,940 1122.99,948 1615,960 1735,965 1830.5,970 2030,980 2200,980 2830,1000 2975,1022.76 2830,1150 885,1170 1810,1190 3040,1190 2690,1220 885,1250 885,1320 1500,1330 2050,1470 2380,1520 1740,1680 945,1800 875,1870 2720,1940 590,1950 810,1950 970,2000 1030,2000 640,2010 2590,2010 2680,2010 3030,2020 3100,2020 970,2060 1030,2060 2590,2100 3100,2100 820,2120 970,2120 1030,2120 3030,2180 3100,2180 2590,2190 2680,2190 545,2230 315,2310 3060,2327 315,2400 2905,2490 880,2500 940,2560 510,2580 590,2580 2820,2615 2535,2760 2715,2760 475,2800 2533,2845 475,2890 1510,3160 1580,3160 680,3240 900,3240 825,3440 915,3440 825,3530 915,3530 1060,3560 1120,3560 1490,3560 1550,3560
  other v2: 2270,800 2300,800 2350,800 2380,800 2270,830 2300,830 2350,830 2380,830 2270,870 2300,870 2350,870 2380,870 2270,900 2300,900 2350,900 2380,900
  other v3: 2545,875 2580,875 2205,1020
IMU_RX: D1.2 J1.A1 R10.1 | length 749.2
  Top Layer w10: R10.1 D1.2 745,3105.24 794.76,3155 998.55,3155 1100,3256.45 1100,3353.68 1124.25,3377.93 1124.25,3477.52 J1.A1
IMU_START: J1.B4 U2.26 | length 2202.4
  Top Layer w8: J1.B4 1285,3260 1086.65,3061.65 1086.65,1798.35 1190,1695 1275,1695 1456.42,1513.58 U2.26
IMU_TX: D2.2 J1.B1 R11.1 | length 475.2
  Top Layer w10: R11.1 D2.2 1004.33,3099.33 1135,3230 J1.B1
LED0: U4.32
LED2: U4.24 | length 2.5
  Top Layer w6: U4.24@2348.26,948.76 U4.24@2350,950.49
LIDAR-PPS: R8.2 R18.2 U2.45 | length 3206.5
  Top Layer w10: v2(405,2655) 405,2245 470,2180 R18.2 470,1907.99 495,1882.99 697.01,1882.99 815,1765 815,1600 920,1495 1315,1495 1421,1389 1421,1262 1558,1125 1840,1125 1850,1135 1850,1200 1824.56,1225.44 1824.56,1265.21 U2.45 ; v2(570,2835) 570,2836.56 572.99,2839.54 572.99,2984.37 578.62,2990 R8.2
  Bottom Layer w10: v2(405,2655) 568.9,2818.9 568.9,2833.9 v2(570,2835)
LIDAR-RX: R17.2 U2.42 | length 1609.6
  Top Layer w10: R17.2@695,1950 695,1925 840,1780 840,1605 930,1515 1325,1515 1440,1400 1440,1275 1500,1215 1755,1215 1765.16,1225.16 U2.42
MDI0_N: T1.11 U4.2 | length 1155.9
  Top Layer w8: T1.11@1355.67,580 1355.67,645.67 1480,770 1775,770 1905,640 2200,640 2269.88,709.88 U4.2
MDI0_P: T1.12 U4.1 | length 1172.5
  Top Layer w8: T1.12@1316.3,580 1316.3,636.3 1470,790 1780,790 1910,660 2201.62,660 2254.13,712.52 U4.1
MDI1_N: T1.8 U4.5 | length 1111.9
  Top Layer w8: T1.8@1473.78,580 1473.78,653.78 1550,730 1765,730 1895,600 2245,600 2317.13,672.13 U4.5
MDI1_P: T1.9 U4.4 | length 1128.2
  Top Layer w8: T1.9@1434.41,580 1434.41,645.59 1538.82,750 1770,750 1900,620 2245,620 2301.38,676.38 U4.4
MDI2_N: T1.5 U4.7 | length 1021.9
  Top Layer w8: T1.5@1591.89,580 1591.89,651.89 1620,680 1765,680 1883.81,561.19 2249.58,561.19 2348.62,660.24 U4.7
MDI2_P: T1.6 U4.6 | length 1039.4
  Top Layer w8: T1.6@1552.52,580 1552.52,642.52 1610,700 1770,700 1890,580 2250,580 2332.87,662.87 U4.6
MDI3_N: T1.2 U4.10 | length 963.4
  Top Layer w8: T1.2@1710,570 1710,630 1720,640 1755,640 1875,520 2260,520 2410,670 2410,715 2395.87,729.13 U4.10
MDI3_P: T1.3 U4.9 | length 979.3
  Top Layer w8: T1.3@1670.63,580 1670.63,639.37 1670,640 1690,660 1760,660 1880,540 2260,540 2391.87,671.87 2391.87,708.08 2380.12,719.84 U4.9
NetC9_2: C9.2 U3.4 | length 79.2
  Top Layer w20: U3.4 3010.43,1105.94 3013.82,1109.33 C9.2@3076.89,1109.33
NetC10_2: C10.2 SL1.13 | length 158.2
  Top Layer w10: SL1.13 1185,958.63 1190.63,953 C10.2
NetC11_2: C11.2 SL1.14 | length 227.7
  Top Layer w12: SL1.14 1237.22,1105.77 1237.22,887.23 C11.2@1241.46,883
NetC14_2: C14.2 USBC1.B2 | length 717
  Top Layer w8: v2(2458.83,441.13) 2460,442.31 2460,530 2620,690 2620,741.46 2603.01,758.45 2603.01,763.37 2596.38,770 C14.2 ; USBC1.B2 2489.43,232.34 2489.43,195.26 v2(2490,194.69)
  Bottom Layer w8: v2(2458.83,441.13) 2475.27,424.69 2490,424.69 v2(2490,194.69)
NetC16_2: C16.2 USBC1.B3 | length 687.6
  Top Layer w8: v2(2460,410) 2440,430 2440,530 2591.46,681.46 C16.2 C16.2@2593.96,712.5 ; USBC1.B3 2469.59,232.5 2469.59,170.1 v2(2470,169.69)
  Bottom Layer w8: v2(2460,410) 2460,179.69 v2(2470,169.69) v2@2470,164.69
NetC19_1: C19.1 T1.1 T1.4 T1.7 T1.10 | length 781.1
  Top Layer w12: C19.1 1392.3,526 1393.15,526.85 ; T1.10 1393.15,526.85 ; T1.7 1510,578.74 1510,520 ; T1.4 1629.37,520.63 ; T1.1 1750,577.48 1750,525 1745.63,520.63 1629.37,520.63 ; 1393.15,526.85 1400,520 1510,520 ; 1510,520 1630,520 1629.37,520.63
NetCY1_2: CY1.2 R6.1 R12.1 R14.1 R19.1 | length 949.7
  Top Layer w12: R6.1 R12.1 1222.18,399 1875,399 1970,399 2050.57,399 CY1.2@2072.58,421.01
NetJ1_B2: J1.B2 R8.1 | length 680.3
  Top Layer w10: R8.1@640,2990 935,2990 1174.25,3229.25 1174.25,3260.98 J1.B2
NetJ2_1: J2.1 Q1.3 R15.1 | length 435.9
  Top Layer w10: J2.1 575.01,2410.42 621.46,2363.97 R15.1 621.46,2221.53 740,2102.99 Q1.3
NetJ2_2: J2.2 Q2.3 R16.1 | length 400.9
  Top Layer w10: J2.2 525.01,2410.42 468.54,2353.95 R16.1 465.63,2292.99 460,2287.36 460,2232.99 550,2142.99 Q2.3
NetJP3_1: JP3.1 T1.13 | length 126.5
  Top Layer w12: T1.13 1314.41,160.59 1349.72,125.28 JP3.1@1349.72,100
NetJP3_2: JP3.2 T1.14 | length 130.6
  Top Layer w12: T1.14 1353.78,171.22 1398.94,126.06 JP3.2@1398.94,100
NetJP3_3: JP3.3 T1.16 | length 120.5
  Top Layer w12: T1.16 1430,209.37 1430,160 1448.15,141.85 JP3.3@1448.15,100
NetJP3_4: JP3.4 T1.17 | length 122.4
  Top Layer w12: T1.17 1471.89,168.11 1497.36,142.64 JP3.4@1497.36,100
NetJP3_5: JP3.5 T1.19 | length 113.6
  Top Layer w12: JP3.5@1546.57,100 1546.57,151.57 1550,155 1550,211.26 T1.19
NetJP3_6: JP3.6 T1.20 | length 114.3
  Top Layer w12: T1.20 1595.79,206.1 JP3.6@1595.79,100
NetJP3_7: JP3.7 T1.22 | length 121.7
  Top Layer w12: JP3.7@1645,100 1645,140 1668.74,163.74 T1.22
NetJP3_8: JP3.8 T1.23 | length 119.2
  Top Layer w12: JP3.8@1694.21,100 1694.21,139.21 1710,155 1710,210 T1.23
NetPC1_K: PC1.2 R3.1 | length 343.4
  Top Layer w8: R3.1 2666.38,1120 2673.01,1126.63 2673.01,1131.55 2720,1178.54 2720,1300 2668.74,1351.26 PC1.2
NetPOW1_K: POW1.2 R2.1 | length 117.3
  Top Layer w8: R2.1 POW1.2
NetQ1_1: Q1.1 R17.1 | length 55.1
  Top Layer w10: R17.1 735.2,1958.18 Q1.1
NetQ2_1: Q2.1 R18.1 | length 60.1
  Top Layer w10: Q2.1 512.6,1953.31 R18.1
NetR4_1: R4.1 U1.9 | length 83.2
  Top Layer w10: R4.1 825,2611 U1.9
NetR6_2: R6.2 T1.15 | length 359.6
  Top Layer w12: R6.2 1135,320 1175,280 1362.04,280 1393.15,248.89 T1.15
NetR7_1: R7.1 U1.11 | length 89.5
  Top Layer w6: U1.11 864,2630.92 882,2612.92 R7.1
NetR10_2: R10.2 U1.26 | length 156.4
  Top Layer w10: R10.2 750,2955.69 750,2930 755,2925 838.14,2925 844,2919.14 U1.26
NetR11_2: R11.2 U1.25 | length 79.4
  Top Layer w10: R11.2 836.13,2960.69 864,2932.82 U1.25
NetR12_2: R12.2 T1.18 | length 403.5
  Top Layer w12: R12.2 1450,355 1511.26,293.74 T1.18
NetR13_1: R13.1 U4.38 | length 125.4
  Top Layer w6: R13.1 2111.97,808.38 2171.58,808.38 2173.83,810.63 U4.38
NetR14_2: R14.2 T1.21 | length 356.5
  Top Layer w12: T1.21 1630,212.52 1630,305 1673.82,348.82 R14.2
NetR19_2: R19.2 T1.24 | length 334.5
  Top Layer w12: T1.24 1750,214.41 1750,270 1780,300 1960,300 1970,310 R19.2
NetSL1_15: SL1.15 X1.2 | length 475.2
  Top Layer w12: X1.2@1143.94,730 1210.06,730 1285,804.94 SL1.15
NetSL1_16: SL1.16 X1.1 | length 378.4
  Top Layer w12: SL1.16 1335,731.06 X1.1@1336.06,730
OSCIN: C15.1 R9.2 U2.5 X2.2 | length 939.7
  Top Layer w10: U2.5 2110.53,1395.47 2187,1319 2187,1218 2215,1190 2305,1190 2325.43,1210.43 R9.2 2325.43,1248.94 2444.58,1368.08 2444.58,1368.51 2476.06,1400 2467.01,1409.05 2467.01,1524.45 C15.1 C15.1@2461.46,1530 ; C15.1@2466.38,1530 C15.1@2472.01,1524.37
OSCOUT: C18.1 R9.1 U2.6 X2.1 | length 651.9
  Top Layer w10: U2.6 2268.78,1415.16 X2.1@2283.94,1400 ; R9.1@2254.57,1245 2259.41,1249.84 2259.41,1375.47 X2.1@2283.94,1400 ; C18.1 2293.54,1409.6 X2.1@2283.94,1400
PA0: FPC1.10 U2.10 | length 1320.8
  Top Layer w8: U2.10 1988.9,1493.9 2085,1590 2730,1590 2918.85,1778.85 FPC1.10
PA1: FPC1.9 U2.11 | length 1291.8
  Top Layer w8: U2.11 1988.58,1513.58 2080,1605 2723.38,1605 2899.15,1780.77 FPC1.9
PA2: FPC1.8 U2.12 | length 1261.8
  Top Layer w8: U2.12 1988.27,1533.27 2075,1620 2715,1620 2879.5,1784.5 FPC1.8
PA3: FPC1.7 U2.13 | length 1269
  Top Layer w8: U2.13 1883.82,1585 1945,1585 1995,1635 2705,1635 2859.85,1789.85 FPC1.7
PA4: FPC1.6 U2.14 | length 1291.8
  Top Layer w8: U2.14 1864.31,1585.18 1864.31,1629.31 1885,1650 2695,1650 2840.15,1795.15 FPC1.6
PA5: FPC1.5 U2.15 | length 1287.9
  Top Layer w8: U2.15 1844.63,1585.18 1844.63,1628.01 1881.62,1665 2685,1665 2820.45,1800.45 FPC1.5
PA6: FPC1.4 U2.16 | length 1292.5
  Top Layer w8: U2.16 1823.48,1585.18 1823.48,1630.14 1823.31,1630.31 1823.31,1638.31 1865,1680 2675,1680 2800.75,1805.75 FPC1.4
PA7: FPC1.3 U2.17 | length 1294.7
  Top Layer w8: U2.17 1804.53,1644.53 1855,1695 2670,1695 2781.05,1806.05 FPC1.3
PC13: R3.2 U2.2 | length 796
  Top Layer w8: U2.2 2013.58,1336.42 2035,1315 2035,1277 2172,1140 2593.62,1140 2613.62,1120 R3.2
PC14: C12.1 U2.3 Y1.1 | length 814.8
  Top Layer w8: U2.3 2024.9,1356.1 2055,1326 2055,1284 2184,1155 2370.98,1155 2410.98,1195 2575.99,1195 2590.99,1180 C12.1
PC15: C13.1 U2.4 Y1.0 | length 825.9
  Top Layer w10: U2.4 2036.21,1375.79 2075,1337 2075,1297 2202,1170 2340.98,1170 2410.98,1240 2603.62,1240 2613.62,1250 C13.1
RESET: C2.2 R1.1 RESET1.2 U2.7 | length 2431.3
  Top Layer w8: U2.7 2069.84,1434.84 2185,1550 2785,1550 3260,2025 3260,2525 3086,2525 3086,2412.46 3080.54,2407
  Top Layer w12: C2.2@3047,2407 3080.54,2407 R1.1@3114.08,2407
SSRX_N: U4.15 USBC1.A10 | length 971
  Top Layer w5: U4.15 2463.95,842.13 2501.69,879.87 2501.69,898.31 2513.45,910.08 2630.08,910.08 2674.5,865.65 2674.5,696.1 2479.02,500.62 USBC1.A10
SSRX_P: U4.16 USBC1.A11 | length 988.2
  Top Layer w6: U4.16 2464.84,857.87 2488.52,881.55 2488.52,900 2516.04,927.51 2627.49,927.51 2685,870 2685,691.75 2498.7,505.45 USBC1.A11
SSTX_N: C16.1 U4.12 | length 164.3
  Top Layer w6: U4.12 2450,794.88 2465,779.88 v2@2465,775 ; v2(2495,740) 2510,740 2540,710 C16.1
  Bottom Layer w6: v2(2462.5,771.81) 2463.19,771.81 v2(2495,740)
SSTX_P: C14.1 U4.13 | length 149
  Top Layer w6: U4.13 2469.37,810.63 v2(2475,805) ; v2(2510,765) 2515,770 C14.1
  Bottom Layer w6: v2(2475,805) 2475,800 v2(2510,765)
SWDCLK: SWD1.2 U2.37 | length 948
  Top Layer w8: SWD1.2@1000,1625 1000,1555 1015,1540 1330,1540 1460,1410 1460,1283 1498,1245 1605,1245 1625.55,1265.55 U2.37
SWDIO: SWD1.3 U2.34 | length 659.2
  Top Layer w8: SWD1.3@1100,1625 1100,1570 1110,1560 1335,1560 1538.9,1356.1 U2.34
U2DM: SL1.5 U4.17 | length 1932.1
  Top Layer w8: SL1.5 1135,1440 1165,1470 1312,1470 1403,1379 1403,1254 1557,1100 2145,1100 2170,1125 2385,1125 2476.52,1033.48 2476.52,886.52 2463.62,873.62 U4.17
U2DP: SL1.6 U4.18 | length 2026.6
  Top Layer w8: SL1.6 1087.99,1339.01 1087.99,1296.7 1099.69,1285 1145,1285 1160,1300 1160,1435 1175,1450 1307,1450 1386,1371 1386,1245 1556,1075 2138.38,1075 2173.38,1110 2381.62,1110 2463.52,1028.09 2463.52,896.52 2456.37,889.37 U4.18
USB3-D_N: SL1.9 USBC1.A7 USBC1.B7 | length 2172.4
  Top Layer w8: SL1.9 985,980 v2(1065,900) ; USBC1.B7 2392.34,231.01 2392.34,207.35 v2(2405,194.69) ; v2(2410,324.69) 2419.89,314.8 2419.89,284.16 USBC1.A7
  Bottom Layer w8: v2(1065,900) 1325,900 1560,665 2280,665 2313,632 2313,547 2411.48,448.52 2411.48,357.07 2411.87,356.68 2411.87,342.7 2411.48,342.31 v2@2411.48,326.17 ; v2(2405,194.69) 2405,196.78 2410,201.78 v2(2410,324.69) v2@2411.48,326.17 ; v2@2413,327.69 v2@2411.48,326.17
USB3-D_P: SL1.10 USBC1.A6 USBC1.B6 | length 2010.7
  Top Layer w8: SL1.10 1035,970 1100,905 v2(1100,875) ; v2(2395,349.69) 2390,344.69 2390,319.69 2400,309.69 2400,284.37 USBC1.A6 2402.19,282.19 2402.19,264.53 2408.21,258.51 2408.21,234.82 USBC1.B6
  Bottom Layer w8: v2(1100,875) 1110,885 1320,885 1555,650 2270,650 2300,620 2300,539.81 2395,444.81 v2(2395,349.69)
VCC: C20.2 JP1.1 USBC1.A4 USBC1.A9 USBC1.B4 USBC1.B9 | length 1112.6
  Top Layer w8: USBC1.A4 2359,282.19 2359,264.54 2352.97,258.51 2352.97,234.82 USBC1.B9 2351.06,188.63 2375,164.69 2425,164.69 2449.49,189.18 USBC1.B4 2451.4,234.82 2451.4,258.51 2457.42,264.53 2457.42,282.19 USBC1.A9
  Top Layer w20: 2425,164.69 2459.69,130 ; JP1.1 2830,251.57 2785,206.57 2606.57,206.57 2530,130 2525.31,130 ; 2459.69,130 2525.31,130 ; 2459.69,130 2460,129.69 2525,129.69 2525.31,130
XTALI: C23.1 U4.35 X3.1 | length 451.8
  Top Layer w8: X3.1 1914.17,887.36 1914.17,944.14 ; C23.1 1914.17,974.37 1914.17,944.14 ; U4.35 2225.85,857.13 2172.87,857.13 2085.86,944.14 1914.17,944.14
XTALO: C24.2 U4.36 X3.3 | length 369.2
  Top Layer w6: C24.2 1970.35,712.63 1970.35,795.54 X3.3 2011.69,796.69 2057.13,842.13 U4.36
pads on no net: J1.A3 J1.A4 J1.A5 J1.A6 J1.A7 J1.B3 J1.B5 J1.B6 J1.B7 J1.MH1 J1.MH2 JP2.0 JP3.0 U1.1 U1.2 U1.10 U1.12 U1.13 U1.14 U1.15 U1.16 U1.17 U1.18 U1.19 U1.20 U1.21 U1.22 U1.23 U1.24 U1.27 U1.28 U1.29 U2.18 U2.19 U2.21 U2.22 U2.25 U2.27 U2.28 U2.29 U2.30 U2.31 U2.38 U2.39 U2.40 U2.41 U2.43 U2.46 U4.28 U4.30 U4.31 USBC1. USBC1.A2 USBC1.A3 USBC1.B10 USBC1.B11

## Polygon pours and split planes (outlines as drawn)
GND on Bottom Layer "GND_L02_P010" (solid, remove dead copper, pour order 10): 980,289.03 980,35 3035,35 3035,311.13
GND on Bottom Layer "GND_L02_P006" (solid, remove dead copper, pour order 6): 170,3884.92 170,221.98 3545,221.98 3545,3876.18
GND on Top Layer "GND_L01_P012" (solid, remove dead copper, pour order 12): 870,268.6 870,35 3010,35 3010,291.61
GND on Top Layer "GND_L01_P008" (solid, remove dead copper, pour order 8): 205,3919.48 205,10.26 3525,10.26 3525,3910.88

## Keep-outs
Keep-Out Layer:
  circle w0.5: c1009.66,2423.98 r62.99
  circle w0.5: c2645.34,2423.98 r62.99
  circle w0.5: c1827.5,3229.97 r62.99
  lines w0.5: 746.12,1523.91 1070.22,10 2924.91,10 3153.42,1077.42 ccw(c3037.93,1102.14) 3096.26,1204.84 cw(c3232.38,1444.47) 3192.79,1717.2 ccw(c3175.82,1834.09) 3286.15,1791.94 ccw(c1815.05,2353.96) 2204.27,3879.91 ccw(c2175.07,3765.46) 2067.07,3813.26 cw(c1815.05,3924.79) 1563.04,3813.26 ccw(c1455.03,3765.46) 1425.84,3879.91 ccw(c1815.05,2353.96) 312.04,1883.89 ccw(c424.77,1919.15) 418.05,1801.23 cw(c397.73,1444.47) 748.11,1514.62 ; 1167.14,1814.83 ccw(c1206.51,1814.83) 1206.51,1775.46 2448.49,1775.46 ccw(c2448.49,1814.83) 2487.86,1814.83 2487.86,3033.12 ccw(c2448.49,3033.12) 2448.49,3072.49 1206.51,3072.49 ccw(c1206.51,3033.12) 1167.14,3033.12 1167.14,1814.83

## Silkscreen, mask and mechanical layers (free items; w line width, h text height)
Top Overlay:
  text "Stereye-0218" at 1390,940 h78.74
Bottom Overlay:
  text "B-" at 1578,146 h80 r90
  text "B+" at 1634,146 h80 r90
  text "D+" at 1408,143 h80 r90
  text "D-" at 1352,142 h80 r90
  text "C+" at 1522,141 h80 r90
  text "C-" at 1465,139 h80 r90
  text "A-" at 1690,139 h80 r90
  text "A+" at 1741,137 h80 r90
Top Solder:
  drawing of 1778 lines, arcs and shapes, not listed

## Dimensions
3185,3901.95 to 3605,-5 on Mechanical 15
